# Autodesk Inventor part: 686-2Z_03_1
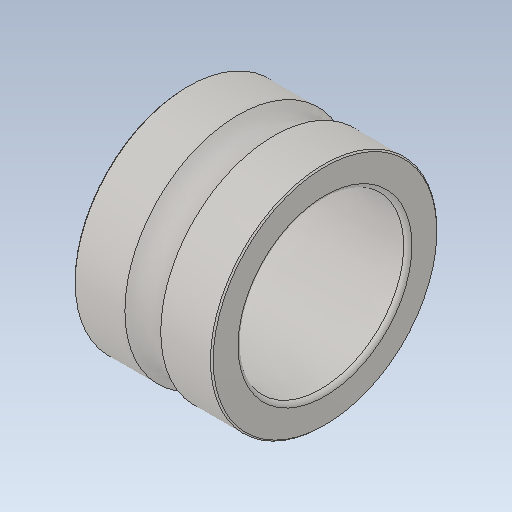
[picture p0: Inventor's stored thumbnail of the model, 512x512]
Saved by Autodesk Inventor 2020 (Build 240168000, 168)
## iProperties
Created: 2017-11
Part Number: 686-2Z_03_1
Material: Ogólny
Document SubType Name: Modeling
Designer: Tomasz
Density: 1 g/cm^3
Appearance: Domyślna
Sending System: SolidWorks 2017
Last Author: Tomasz
Last Saved: 2017-11-19
Source: 686-2Z_03_1
Author: Tomasz
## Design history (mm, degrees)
feature "Imported1"
node "Bryła1"
